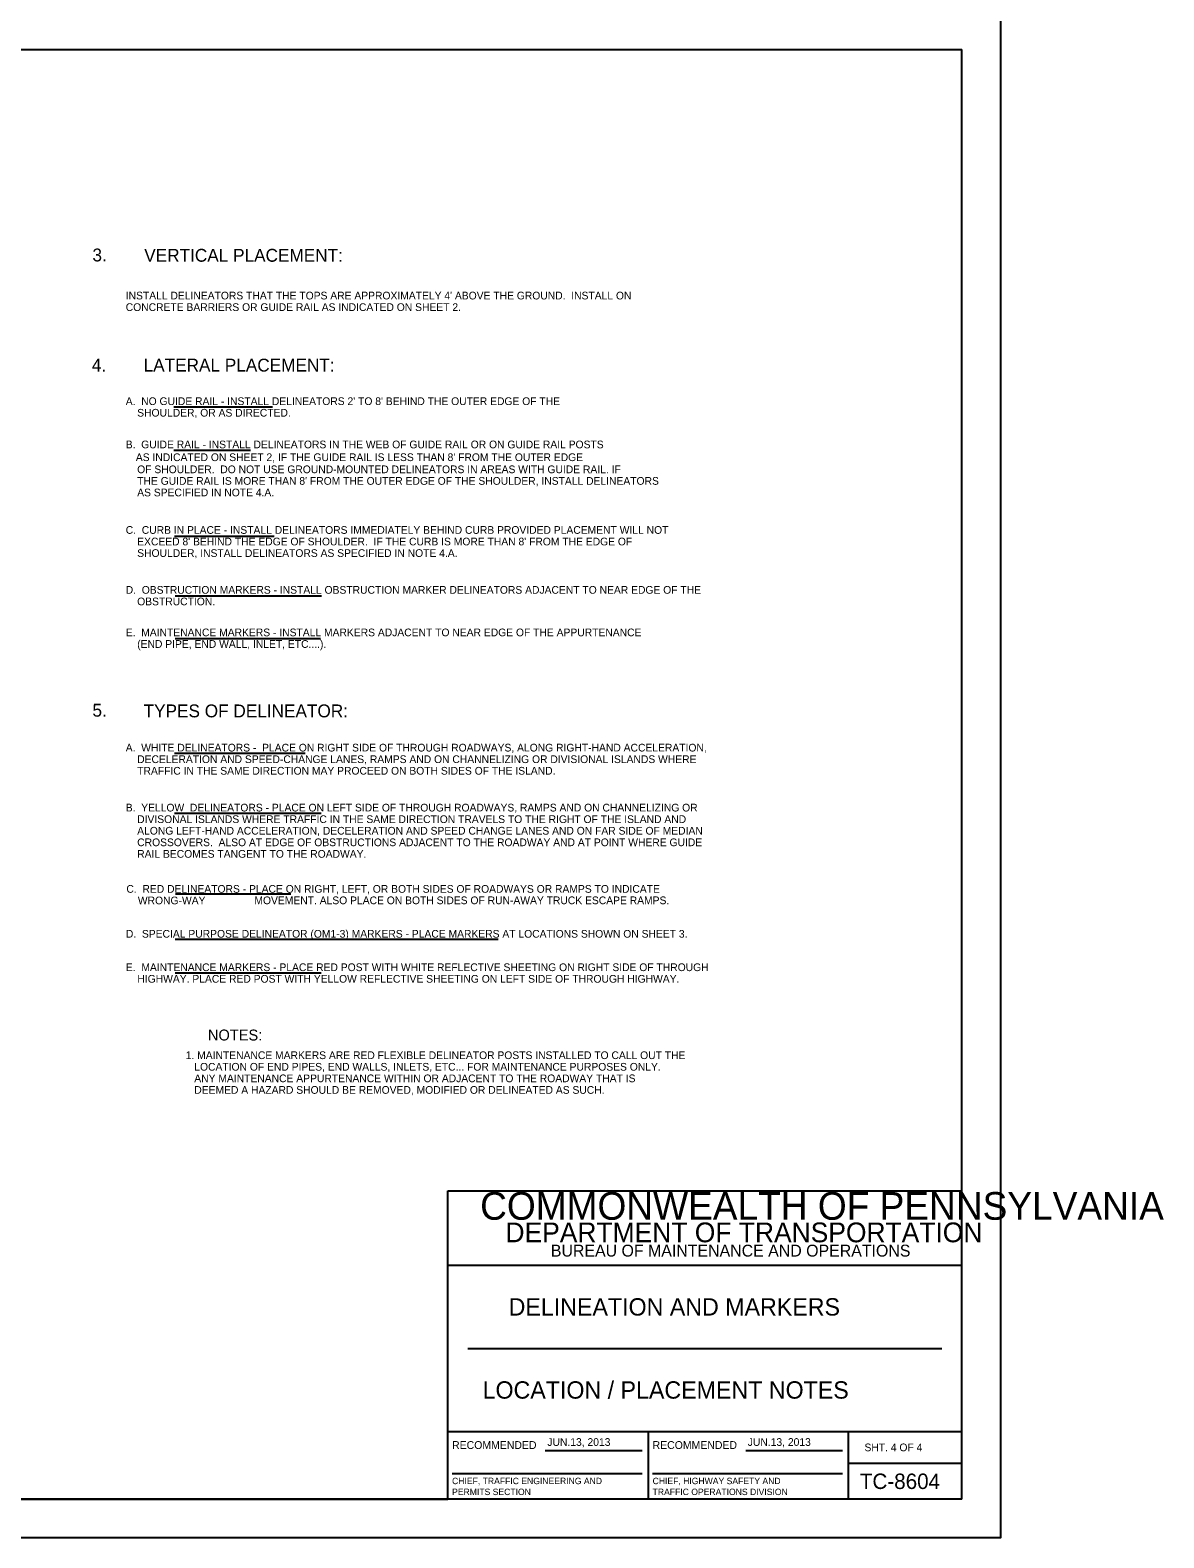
# Model space of a CAD drawing. Extents: x 640253 to 641999, y 298458 to 299646.
# Drawn here: x 641558 to 641999, y 298458 to 299044 of the extents above; entities that cross this region are included whole.
import ezdxf

# ---------------------------------------------------------------- set-up
doc = ezdxf.new("R2010")
doc.units = 0
for name, color, linetype in [('1', 7, 'Continuous'), ('2', 7, 'Continuous'), ('Level 1', 7, 'Continuous'), ('PLT-BNDY', 7, 'Continuous')]:
    doc.layers.add(name, color=color, linetype=linetype)

msp = doc.modelspace()

# ---------------------------------------------------------------- linework, layer by layer
at = {"layer": '1'}
for p, q in [((641134.31, 299036.63), (641920.31, 299036.63)), ((641920.31, 298472.63), (641920.31, 299036.63)), ((641720.31, 298472.63), (641720.31, 298592.63)), ((641720.31, 298592.63), (641920.31, 298592.63)), ((641920.31, 298563.63), (641720.31, 298563.63)), ((641728.06, 298531.31), (641912.56, 298531.31)), ((641720.31, 298499), (641920.31, 298499)), ((641798.31, 298499), (641798.31, 298472.63)), ((641876.19, 298472.63), (641876.19, 298499)), ((641758.24, 298491.57), (641795.87, 298491.57)), ((641836.24, 298491.57), (641873.87, 298491.57)), ((641876.19, 298486.63), (641920.31, 298486.63)), ((641920.31, 298472.63), (641134.31, 298472.63)), ((641134.31, 298472.63), (641720.31, 298472.63))]:
    msp.add_line(p, q, dxfattribs=at)
at = {"layer": '2'}
for p, q in [((641613.73, 298897.59), (641652.08, 298897.59)), ((641613.73, 298880.68), (641643.54, 298880.68)), ((641613.99, 298847.24), (641652.76, 298847.24)), ((641614.25, 298824.09), (641671.21, 298824.09)), ((641614.25, 298807.53), (641670.78, 298807.53)), ((641613.99, 298762.89), (641664.87, 298762.89)), ((641613.99, 298739.54), (641671.05, 298739.54)), ((641614.46, 298708.18), (641659.32, 298708.18)), ((641614.33, 298690.48), (641739.94, 298690.48)), ((641614.33, 298677.47), (641671.03, 298677.47))]:
    msp.add_line(p, q, dxfattribs=at)
at = {"layer": 'Level 1'}
for p, q in [((641721.99, 298482.68), (641795.87, 298482.68)), ((641799.99, 298482.68), (641873.87, 298482.68))]:
    msp.add_line(p, q, dxfattribs=at)
at = {"layer": 'PLT-BNDY'}
msp.add_lwpolyline([(641094.31, 299051.63), (641935.31, 299051.63), (641935.31, 298457.63), (641094.31, 298457.63)], close=True, dxfattribs=at)

# ---------------------------------------------------------------- texts
at = {"layer": '1'}
for s, height, p in [('COMMONWEALTH OF PENNSYLVANIA', 10.7828, (641732.9, 298581.36)), ('DEPARTMENT OF TRANSPORTATION', 7.6837, (641742.76, 298572.61)), ('BUREAU OF MAINTENANCE AND OPERATIONS', 4.6253, (641760.41, 298567.04)), ('DELINEATION AND MARKERS', 6.75, (641743.99, 298544.1)), ('LOCATION / PLACEMENT NOTES', 6.75, (641733.86, 298511.78)), ('RECOMMENDED', 3.048, (641721.99, 298492.2)), ('JUN.13, 2013', 3, (641759.05, 298493.4)), ('RECOMMENDED', 3.048, (641799.99, 298492.2)), ('JUN.13, 2013', 3, (641837.01, 298493.4)), ('SHT. 4 OF 4', 3, (641882.4, 298491.31)), ('TC-8604', 6, (641880.6, 298476.63))]:
    msp.add_text(s, height=height, dxfattribs=at).set_placement(p)
at = {"layer": '2'}
for s, height, p in [('3.', 5, (641582.09, 298954.17)), ('VERTICAL PLACEMENT:', 5, (641602.24, 298954.04)), ("    INSTALL DELINEATORS THAT THE TOPS ARE APPROXIMATELY 4' ABOVE THE GROUND.  INSTALL ON ", 3, (641590.58, 298939.38)), ('    CONCRETE BARRIERS OR GUIDE RAIL AS INDICATED ON SHEET 2.', 3, (641590.58, 298934.88)), ('4.', 5, (641581.84, 298911.32)), ('LATERAL PLACEMENT:', 5, (641601.99, 298911.32)), ("    A.  NO GUIDE RAIL - INSTALL DELINEATORS 2' TO 8' BEHIND THE OUTER EDGE OF THE ", 3, (641590.58, 298898.29)), ('        SHOULDER, OR AS DIRECTED.', 3, (641590.58, 298893.79)), ('    B.  GUIDE RAIL - INSTALL DELINEATORS IN THE WEB OF GUIDE RAIL OR ON GUIDE RAIL POSTS', 3, (641590.58, 298881.46)), ("        AS INDICATED ON SHEET 2, IF THE GUIDE RAIL IS LESS THAN 8' FROM THE OUTER EDGE", 3, (641590.05, 298876.49)), ('        OF SHOULDER.  DO NOT USE GROUND-MOUNTED DELINEATORS IN AREAS WITH GUIDE RAIL. IF', 3, (641590.58, 298871.78)), ("        THE GUIDE RAIL IS MORE THAN 8' FROM THE OUTER EDGE OF THE SHOULDER, INSTALL DELINEATORS", 3, (641590.58, 298867.28)), ('        AS SPECIFIED IN NOTE 4.A. ', 3, (641590.58, 298862.78)), ('    C.  CURB IN PLACE - INSTALL DELINEATORS IMMEDIATELY BEHIND CURB PROVIDED PLACEMENT WILL NOT', 3, (641590.58, 298848.2)), ("        EXCEED 8' BEHIND THE EDGE OF SHOULDER.  IF THE CURB IS MORE THAN 8' FROM THE EDGE OF ", 3, (641590.58, 298843.7)), ('        SHOULDER, INSTALL DELINEATORS AS SPECIFIED IN NOTE 4.A.    ', 3, (641590.58, 298839.2)), ('    D.  OBSTRUCTION MARKERS - INSTALL OBSTRUCTION MARKER DELINEATORS ADJACENT TO NEAR EDGE OF THE', 3, (641590.58, 298824.89)), ('        OBSTRUCTION.', 3, (641590.58, 298820.39)), ('    E.  MAINTENANCE MARKERS - INSTALL MARKERS ADJACENT TO NEAR EDGE OF THE APPURTENANCE', 3, (641590.58, 298808.34)), ('        (END PIPE, END WALL, INLET, ETC....).', 3, (641590.58, 298803.84)), ('5.', 5, (641582.09, 298777.07)), ('TYPES OF DELINEATOR:', 5, (641601.99, 298776.81)), ('    A.  WHITE DELINEATORS -  PLACE ON RIGHT SIDE OF THROUGH ROADWAYS, ALONG RIGHT-HAND ACCELERATION,', 3, (641590.58, 298763.52)), ('        TRAFFIC IN THE SAME DIRECTION MAY PROCEED ON BOTH SIDES OF THE ISLAND.', 3, (641590.58, 298754.52)), ('        DECELERATION AND SPEED-CHANGE LANES, RAMPS AND ON CHANNELIZING OR DIVISIONAL ISLANDS WHERE', 3, (641590.58, 298759.02)), ('    B.  YELLOW  DELINEATORS - PLACE ON LEFT SIDE OF THROUGH ROADWAYS, RAMPS AND ON CHANNELIZING OR', 3, (641590.58, 298740.19)), ('        ALONG LEFT-HAND ACCELERATION, DECELERATION AND SPEED CHANGE LANES AND ON FAR SIDE OF MEDIAN', 3, (641590.58, 298731.19)), ('        DIVISONAL ISLANDS WHERE TRAFFIC IN THE SAME DIRECTION TRAVELS TO THE RIGHT OF THE ISLAND AND', 3, (641590.58, 298735.69)), ('        CROSSOVERS.  ALSO AT EDGE OF OBSTRUCTIONS ADJACENT TO THE ROADWAY AND AT POINT WHERE GUIDE', 3, (641590.58, 298726.69)), ('        RAIL BECOMES TANGENT TO THE ROADWAY.', 3, (641590.58, 298722.19)), ('    C.  RED DELINEATORS - PLACE ON RIGHT, LEFT, OR BOTH SIDES OF ROADWAYS OR RAMPS TO INDICATE', 3, (641590.84, 298708.57)), ('        WRONG-WAY ', 3, (641590.84, 298704.07)), ('MOVEMENT. ALSO PLACE ON BOTH SIDES OF RUN-AWAY TRUCK ESCAPE RAMPS.', 3, (641645.09, 298704.12)), ('    D.  SPECIAL PURPOSE DELINEATOR (OM1-3) MARKERS - PLACE MARKERS AT LOCATIONS SHOWN ON SHEET 3.', 3, (641590.64, 298691.1)), ('    E.  MAINTENANCE MARKERS - PLACE RED POST WITH WHITE REFLECTIVE SHEETING ON RIGHT SIDE OF THROUGH', 3, (641590.64, 298678.09)), ('        HIGHWAY. PLACE RED POST WITH YELLOW REFLECTIVE SHEETING ON LEFT SIDE OF THROUGH HIGHWAY.', 3, (641590.64, 298673.59)), ('NOTES:', 4.25, (641627, 298651.1)), ('1. MAINTENANCE MARKERS ARE RED FLEXIBLE DELINEATOR POSTS INSTALLED TO CALL OUT THE', 3, (641618.36, 298643.87)), ('   LOCATION OF END PIPES, END WALLS, INLETS, ETC... FOR MAINTENANCE PURPOSES ONLY.', 3, (641618.36, 298639.37)), ('   ANY MAINTENANCE APPURTENANCE WITHIN OR ADJACENT TO THE ROADWAY THAT IS', 3, (641618.36, 298634.87)), ('   DEEMED A HAZARD SHOULD BE REMOVED, MODIFIED OR DELINEATED AS SUCH.', 3, (641618.36, 298630.37))]:
    msp.add_text(s, height=height, dxfattribs=at).set_placement(p)
at = {"layer": 'Level 1'}
for s, p in [('CHIEF, TRAFFIC ENGINEERING AND', (641721.99, 298478.51)), ('PERMITS SECTION', (641721.99, 298474.26)), ('TRAFFIC OPERATIONS DIVISION', (641799.99, 298474.26)), ('CHIEF, HIGHWAY SAFETY AND', (641799.99, 298478.51))]:
    msp.add_text(s, height=2.5, dxfattribs=at).set_placement(p)

doc.saveas('drawing.dxf')
